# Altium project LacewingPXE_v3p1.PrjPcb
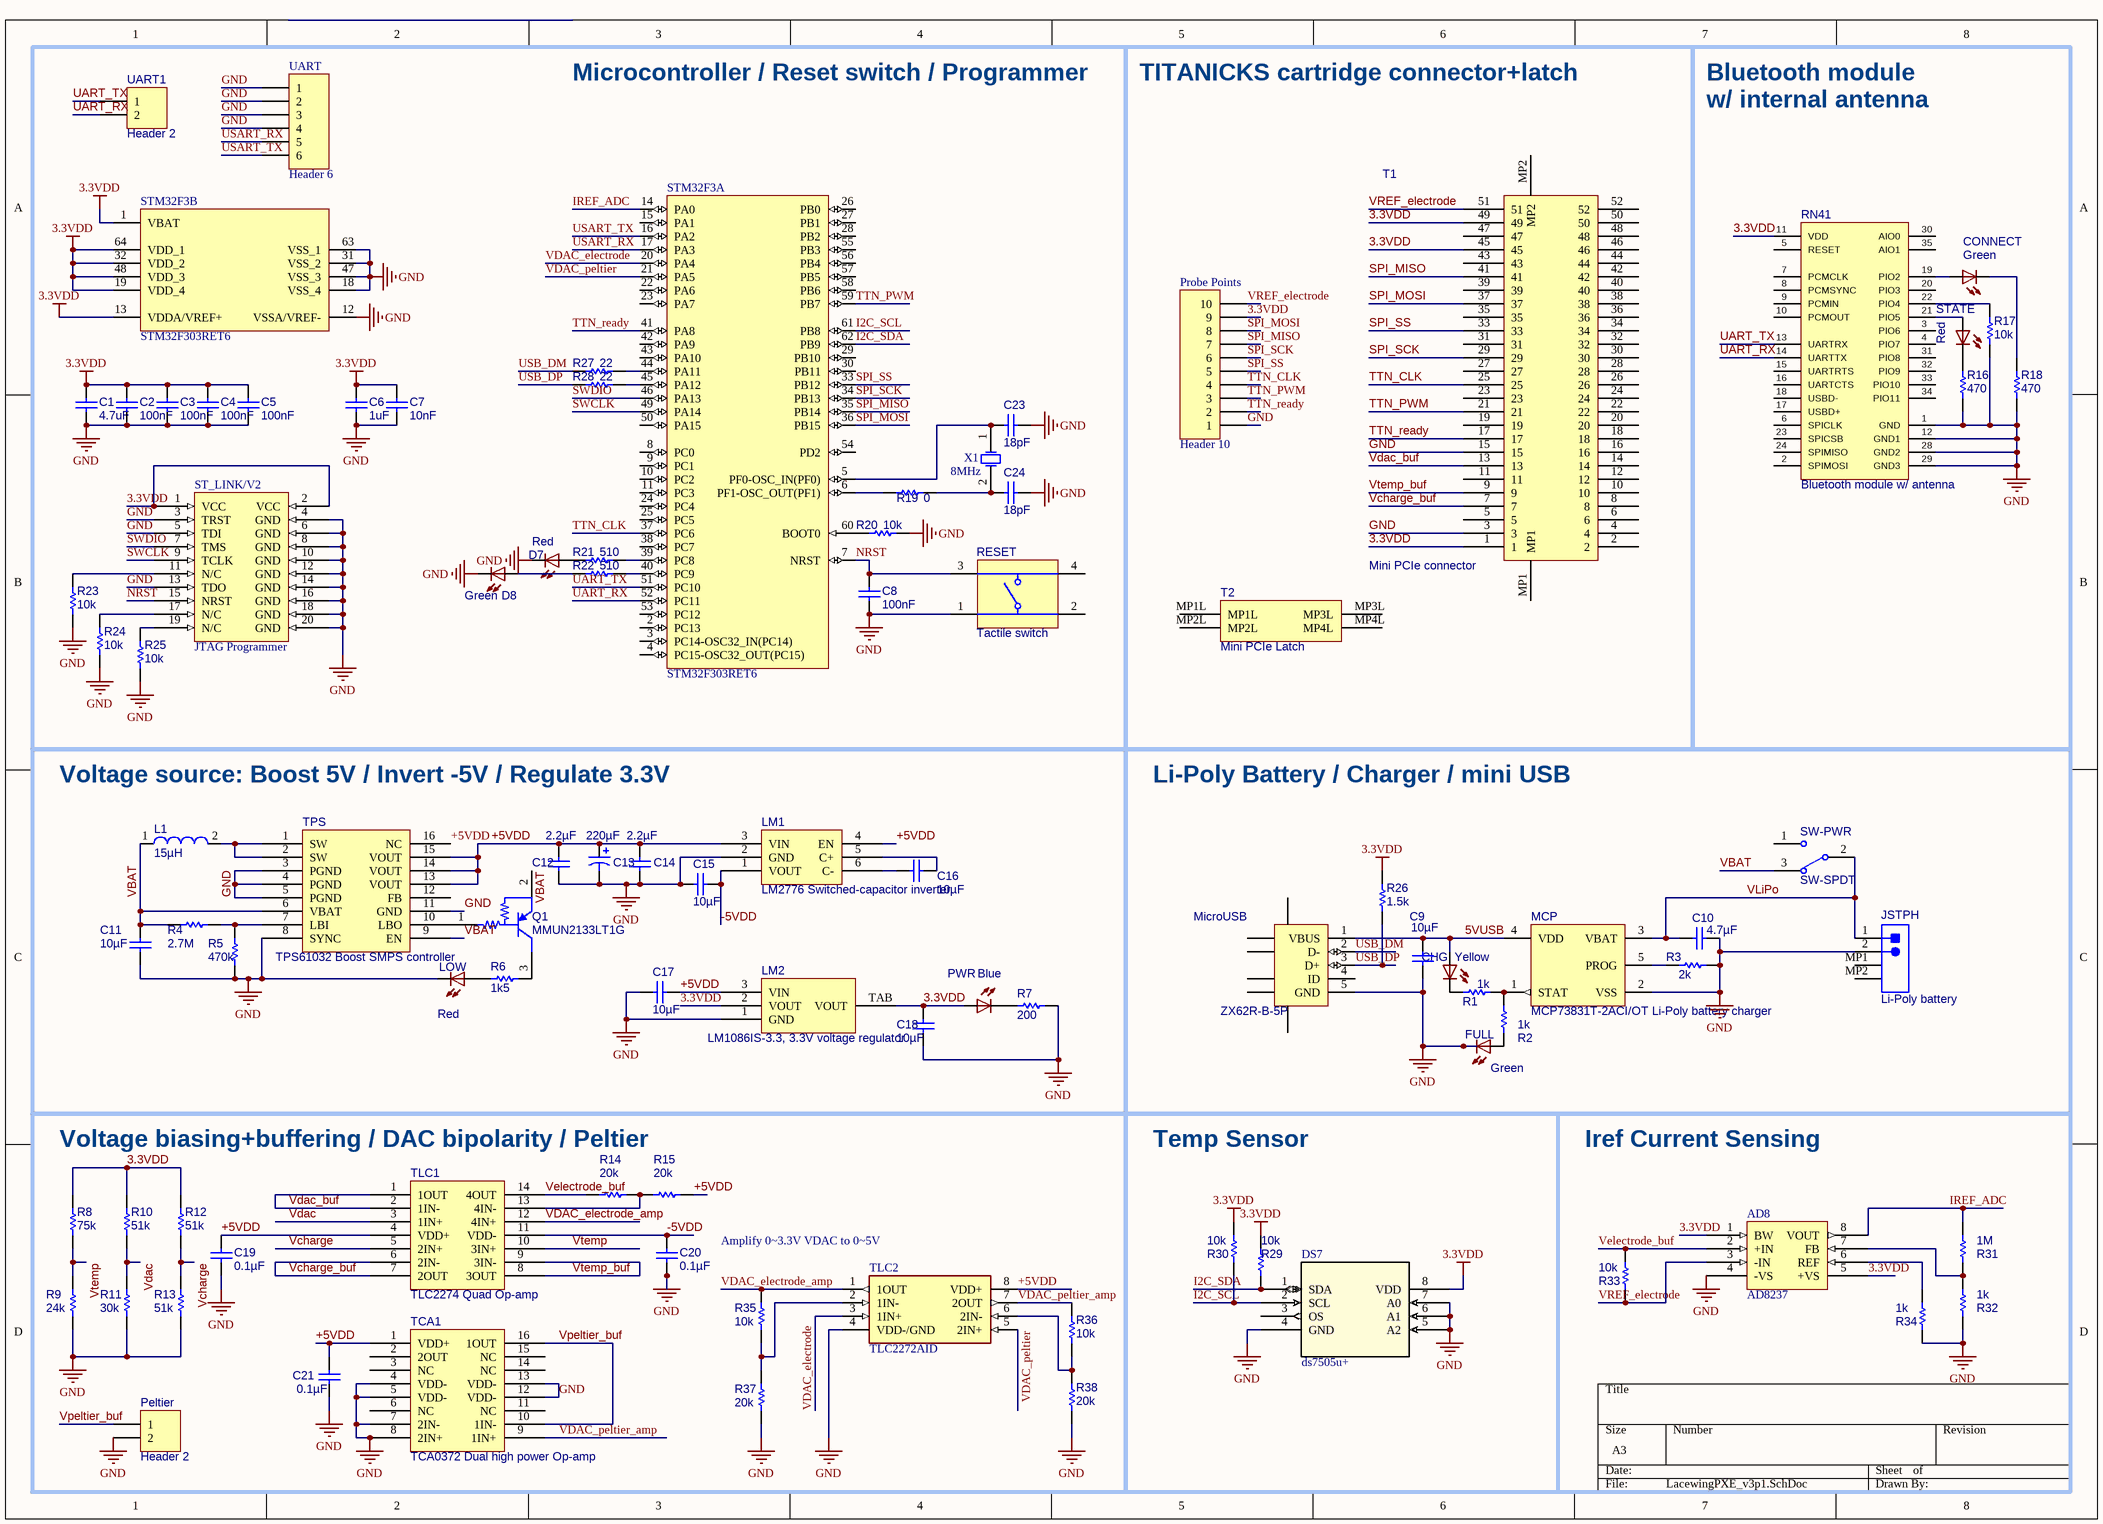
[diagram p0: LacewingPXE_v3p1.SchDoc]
1 sheet, 94 parts. Net scope: global (net labels, ports and power ports of the same name join across sheets).
Board file: LacewingPXE_v3p1.PcbDoc

## Sheet LacewingPXE_v3p1.SchDoc
size A3

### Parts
AD8  AD8237  [ADI-RM-8_N]
C1  4.7uF  [CAPC0603(1608)100_N]
C2  100nF  [CAPC0603(1608)100_N]
C3  100nF  [CAPC0603(1608)100_N]
C4  100nF  [CAPC0603(1608)100_N]
C5  100nF  [CAPC0603(1608)100_N]
C6  1uF  [CAPC0603(1608)100_N]
C7  10nF  [CAPC0603(1608)100_N]
C8  100nF  [CAPC0603(1608)100_N]
C9  10µF  [CAPC0805(2012)75_N]
C10  4.7µF  [CAPC0603(1608)100_N]
C11  10µF  [CAPC0805(2012)75_N]
C12  2.2µF  [CAPC0805(2012)75_N]
C13  220µF  [AVX-CAPC7343_V]
C14  2.2µF  [CAPC0805(2012)75_N]
C15  10µF  [CAPC0805(2012)75_N]
C16  10µF  [CAPC0805(2012)75_N]
C17  10µF  [CAPC0805(2012)75_N]
C18  10µF  [CAPC0805(2012)75_N]
C19  0.1µF  [CAPC0603(1608)100_N]
C20  0.1µF  [CAPC0603(1608)100_N]
C21  0.1µF  [CAPC0603(1608)100_N]
C23  18pF  [CAPC0603(1608)100_N]
C24  18pF  [CAPC0603(1608)100_N]
CHG  Yellow  [LED-0603]
CONNECT  Green  [LED-0603]
D7  Red  [LED-0603]
D8  Green  [LED-0603]
DS7  ds7505u+  [21-0036K]
FULL  Green  [LED-0603]
JSTPH  Li-Poly battery  [JST- S2B-PH-SM4-TB(LF)(SN)-2_V]
L1  15µH  [WE-PD 1050]
LM1  LM2776 Switched-capacitor inverter  [TI-DBV6_M]
LM2  LM1086IS-3.3, 3.3V voltage regulator  [TS3B_M]
LOW  Red  [LED-0603]
MCP  MCP73831T-2ACI/OT Li-Poly battery charger  [SOT-23-OT5_M]
MicroUSB  ZX62R-B-5P  [HIRO-ZX62R-B-5P_V]
Peltier  Header 2  [HDR1X2]
Probe_Points  Header 10  [HDR1X10]
PWR  Blue  [LED-0603]
Q1  MMUN2133LT1G  [ONSC-SOT-23-3-318-08_V]
R1  1k  [RESC0603(1608)_N]
R2  1k  [RESC0603(1608)_N]
R3  2k  [RESC0603(1608)_N]
R4  2.7M  [RESC0603(1608)_N]
R5  470k  [RESC0603(1608)_N]
R6  1k5  [RESC0603(1608)_N]
R7  200  [RESC0603(1608)_N]
R8  75k  [RESC0603(1608)_N]
R9  24k  [RESC0603(1608)_N]
R10  51k  [RESC0603(1608)_N]
R11  30k  [RESC0603(1608)_N]
R12  51k  [RESC0603(1608)_N]
R13  51k  [RESC0603(1608)_N]
R14  20k  [RESC0603(1608)_N]
R15  20k  [RESC0603(1608)_N]
R16  470  [RESC0603(1608)_N]
R17  10k  [RESC0603(1608)_N]
R18  470  [RESC0603(1608)_N]
R19  0  [RESC0603(1608)_N]
R20  10k  [RESC0603(1608)_N]
R21  510  [RESC0603(1608)_N]
R22  510  [RESC0603(1608)_N]
R23  10k  [RESC0603(1608)_N]
R24  10k  [RESC0603(1608)_N]
R25  10k  [RESC0603(1608)_N]
R26  1.5k  [RESC0603(1608)_N]
R27  22  [RESC0603(1608)_N]
R28  22  [RESC0603(1608)_N]
R29  10k  [RESC0603(1608)_N]
R30  10k  [RESC0603(1608)_N]
R31  1M  [RESC0603(1608)_N]
R32  1k  [RESC0603(1608)_N]
R33  10k  [RESC0603(1608)_N]
R34  1k  [RESC0603(1608)_N]
R35  10k  [RESC0603(1608)_N]
R36  10k  [RESC0603(1608)_N]
R37  20k  [RESC0603(1608)_N]
R38  20k  [RESC0603(1608)_N]
RESET  Tactile switch  [OMRON-B3F-1000-4_V]
RN41  Bluetooth module w/ antenna  [RN41]
ST_LINK/V2  JTAG Programmer  [JTAG2]
STATE  Red  [LED-0603]
STM32F3  STM32F303RET6  [STM-LQFP64_V]  (parts A,B of 2)
SW-PWR  SW-SPDT  [SWITCH SPDT CS12ANW03]
T1  Mini PCIe connector  [Molex Conn-67910]
T2  Mini PCIe Latch  [Molex Latch-48099]
TCA1  TCA0372 Dual high power Op-amp  [ONSC-SOIC-16-751G-03_V]
TLC1  TLC2274 Quad Op-amp  [TI-D14_M]
TLC2  TLC2272AID  [SOIC127P600X175-8N]
TPS  TPS61032 Boost SMPS controller  [PW0016A_M]
UART  Header 6  [HDR1X6]
UART1  Header 2  [HDR1X2]
X1  8MHz  [QCL]

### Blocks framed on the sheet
Microcontroller / Reset switch / Programmer: C1-C8 C23 C24 D7 D8 R19-R25 R27 R28 RESET ST_LINK/V2 STM32F3 UART UART1 X1
TITANICKS cartridge connector+latch: Probe_Points T1 T2
Voltage source: Boost 5V / Invert -5V / Regulate 3.3V: C11-C18 L1 LM1 LM2 LOW PWR Q1 R4-R7 TPS
Li-Poly Battery / Charger / mini USB: C9 C10 CHG FULL JSTPH MCP MicroUSB R1-R3 R26 SW-PWR
Voltage biasing+buffering / DAC bipolarity / Peltier: C19-C21 Peltier R8-R15 R35-R38 TCA1 TLC1 TLC2

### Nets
3.3VDD: AD8.1(BW) AD8.5(+VS) C1.1 C2.1 C3.1 C4.1 C5.1 C6.1 C7.1 C18.2 DS7.8(VDD) LM2.2(VOUT) LM2.TAB(VOUT) Probe_Points.9 PWR.A R8.1 R10.1 R12.1 R26.2 R29.2 R30.2 RN41.11(VDD) ST_LINK/V2.1(VCC) ST_LINK/V2.2(VCC) STM32F3.1(VBAT) STM32F3.13(VDDA/VREF+) STM32F3.19(VDD_4) STM32F3.32(VDD_2) STM32F3.48(VDD_3) STM32F3.64(VDD_1) T1.1 T1.45 T1.49
GND: AD8.4(-VS) C1.2 C2.2 C3.2 C4.2 C5.2 C6.2 C7.2 C8.2 C9.1 C10.1 C11.1 C12.1 C13.2 C14.1 C15.2 C17.2 C18.1 C19.1 C20.1 C21.1 C23.2 C24.2 D7.C D8.C DS7.4(GND) DS7.5(A2) DS7.6(A1) DS7.7(A0) FULL.C JSTPH.2 LM1.2(GND) LM2.1(GND) LOW.C MCP.2(VSS) MicroUSB.5(GND) Peltier.2 Probe_Points.1 R3.2 R5.2 R7.2 R9.2 R11.2 R13.2 R16.1 R17.1 R18.1 R20.2 R23.1 R24.1 R25.1 R32.1 R34.1 R37.1 R38.1 RESET.1 RN41.1(GND) RN41.12(GND1) RN41.28(GND2) RN41.29(GND3) ST_LINK/V2.3(TRST) ST_LINK/V2.4(GND) ST_LINK/V2.5(TDI) ST_LINK/V2.6(GND) ST_LINK/V2.8(GND) ST_LINK/V2.10(GND) ST_LINK/V2.12(GND) ST_LINK/V2.13(TDO) ST_LINK/V2.14(GND) ST_LINK/V2.16(GND) ST_LINK/V2.18(GND) ST_LINK/V2.20(GND) STM32F3.12(VSSA/VREF-) STM32F3.18(VSS_4) STM32F3.31(VSS_2) STM32F3.47(VSS_3) STM32F3.63(VSS_1) T1.3 T1.15 TCA1.4(VDD-) TCA1.5(VDD-) TCA1.7(2IN-) TCA1.8(2IN+) TCA1.12(VDD-) TCA1.13(VDD-) TLC2.4(VDD-/GND) TPS.3(PGND) TPS.4(PGND) TPS.5(PGND) TPS.8(SYNC) TPS.11(GND) UART.1 UART.2 UART.3 UART.4
5VUSB: C9.2 CHG.A MCP.4(VDD) MicroUSB.1(VBUS)
+5VDD: C12.2 C13.1 C14.2 C17.1 C19.2 C21.2 LM1.3(VIN) LM1.4(EN) LM2.3(VIN) R15.2 TCA1.1(VDD+) TLC1.4(VDD+) TLC2.8(VDD+) TPS.13(VOUT) TPS.14(VOUT) TPS.15(VOUT) TPS.16(NC)
-5VDD: C15.1 C20.2 LM1.1(VOUT) TLC1.11(VDD-)
I2C_SCL: DS7.2(SCL) R30.1 STM32F3.61(PB8)
I2C_SDA: DS7.1(SDA) R29.1 STM32F3.62(PB9)
IREF_ADC: AD8.8(VOUT) R31.2 STM32F3.14(PA0)
NRST: C8.1 RESET.3 ST_LINK/V2.15(NRST) STM32F3.7(NRST)
SPI_MISO: Probe_Points.7 STM32F3.35(PB14) T1.41
SPI_MOSI: Probe_Points.8 STM32F3.36(PB15) T1.37
SPI_SCK: Probe_Points.6 STM32F3.34(PB13) T1.29
SPI_SS: Probe_Points.5 STM32F3.33(PB12) T1.33
SWCLK: ST_LINK/V2.9(TCLK) STM32F3.49(PA14)
SWDIO: ST_LINK/V2.7(TMS) STM32F3.46(PA13)
TTN_CLK: Probe_Points.4 STM32F3.37(PC6) T1.25
TTN_PWM: Probe_Points.3 STM32F3.59(PB7) T1.21
TTN_ready: Probe_Points.2 STM32F3.41(PA8) T1.17
UART_RX: RN41.14(UARTTX) STM32F3.52(PC11) UART1.2
UART_TX: RN41.13(UARTRX) STM32F3.51(PC10) UART1.1
USART_RX: STM32F3.17(PA3) UART.5
USART_TX: STM32F3.16(PA2) UART.6
USB_DM: MicroUSB.2(D-) R27.1
USB_DP: MicroUSB.3(D+) R26.1 R28.1
VBAT: C11.2 L1.1 Q1.2(E) R4.2 SW-PWR.3 TPS.6(VBAT) TPS.9(EN)
Vcharge: R12.2 R13.1 TLC1.5(2IN+)
Vcharge_buf: T1.7 TLC1.6(2IN-) TLC1.7(2OUT)
Vdac: R10.2 R11.1 TLC1.3(1IN+)
Vdac_buf: T1.13 TLC1.1(1OUT) TLC1.2(1IN-)
VDAC_electrode: STM32F3.20(PA4) TLC2.3(1IN+)
VDAC_electrode_amp: R35.2 TLC1.12(4IN+) TLC2.1(1OUT)
VDAC_peltier: STM32F3.21(PA5) TLC2.5(2IN+)
VDAC_peltier_amp: R36.2 TCA1.9(1IN+) TLC2.7(2OUT)
Velectrode_buf: AD8.2(+IN) R14.1 R33.2 TLC1.14(4OUT)
VLiPo: C10.2 JSTPH.1 MCP.3(VBAT) SW-PWR.2
Vpeltier_buf: Peltier.1 TCA1.10(1IN-) TCA1.16(1OUT)
VREF_electrode: AD8.3(-IN) Probe_Points.10 R33.1 T1.51
Vtemp: R8.2 R9.1 TLC1.10(3IN+)
Vtemp_buf: T1.9 TLC1.8(3OUT) TLC1.9(3IN-)
NetAD8_6: AD8.6(REF) R34.2
NetAD8_7: AD8.7(FB) R31.1 R32.2
NetC16_1: C16.1 LM1.5(C+)
NetC16_2: C16.2 LM1.6(C-)
NetC23_1: C23.1 STM32F3.5(PF0-OSC_IN(PF0)) X1.1(OSC1)
NetC24_1: C24.1 R19.1 X1.2(OSC2)
NetCHG_C: CHG.C R1.1
NetCONNECT_A: CONNECT.A RN41.19(PIO2)
NetCONNECT_C: CONNECT.C R18.2
NetD7_A: D7.A R21.1
NetD8_A: D8.A R22.1
NetFULL_A: FULL.A R2.1
NetL1_2: L1.2 TPS.1(SW) TPS.2(SW)
NetLOW_A: LOW.A R6.1
NetMCP_1: MCP.1(STAT) R1.2 R2.2
NetMCP_5: MCP.5(PROG) R3.1
NetPWR_C: PWR.C R7.1
NetQ1_1: Q1.1(B) TPS.10(LBO)
NetQ1_3: Q1.3(C) R6.2
NetR4_1: R4.1 R5.1 TPS.7(LBI)
NetR14_2: R14.2 R15.1 TLC1.13(4IN-)
NetR16_2: R16.2 STATE.C
NetR17_2: R17.2 RN41.22(PIO4)
NetR19_2: R19.2 STM32F3.6(PF1-OSC_OUT(PF1))
NetR20_1: R20.1 STM32F3.60(BOOT0)
NetR21_2: R21.2 STM32F3.39(PC8)
NetR22_2: R22.2 STM32F3.40(PC9)
NetR23_2: R23.2 ST_LINK/V2.11(N/C)
NetR24_2: R24.2 ST_LINK/V2.17(N/C)
NetR25_2: R25.2 ST_LINK/V2.19(N/C)
NetR27_2: R27.2 STM32F3.44(PA11)
NetR28_2: R28.2 STM32F3.45(PA12)
NetR35_1: R35.1 R37.2 TLC2.2(1IN-)
NetR36_1: R36.1 R38.2 TLC2.6(2IN-)
NetRN41_21: RN41.21(PIO5) STATE.A

Not connected (* = marked no-connect by the designer): DS7 3(OS); JSTPH MP1 MP2; MicroUSB 4(ID) 6(SHLD) 7(SHLD) 8(SHLD) 9(SHLD) 10(SHLD) 11(SHLD); RESET 2 4; RN41 2(SPIMOSI) 3(PIO6) 4(PIO7) 5(RESET) 6(SPICLK) 7(PCMCLK) 8(PCMSYNC) 9(PCMIN) 10(PCMOUT) 15(UARTRTS) 16(UARTCTS) 17(USBD+) 18(USBD-) 20(PIO3) 23(SPICSB) 24(SPIMISO) 30(AIO0) 31(PIO8) 32(PIO9) 33(PIO10) 34(PIO11) 35(AIO1); STM32F3 2(PC13) 3(PC14-OSC32_IN(PC14)) 4(PC15-OSC32_OUT(PC15)) 8(PC0) 9(PC1) 10(PC2) 11(PC3) 15(PA1) 22(PA6) 23(PA7) 24(PC4) 25(PC5) 26(PB0) 27(PB1) 28(PB2) 29(PB10) 30(PB11) 38(PC7) 42(PA9) 43(PA10) 50(PA15) 53(PC12) 54(PD2) 55(PB3) 56(PB4) 57(PB5) 58(PB6); SW-PWR 1; T1 2 4 5 6 8 10 11 12 14 16 18 19 20 22 23 24 26 27 28 30 31 32 34 35 36 38 39 40 42 43 44 46 47 48 50 52 MP1 MP2; T2 MP1L MP2L MP3L MP4L; TCA1 2(2OUT) 3(NC) 6(NC) 11(NC) 14(NC) 15(NC); TPS 12(FB)

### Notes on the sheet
- Bluetooth module
- w/ internal antenna
- Temp Sensor
- Iref Current Sensing
- Amplify 0~3.3V VDAC to 0~5V

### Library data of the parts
C1-C8 C23 C24 = CMP-1035-00032-1: Ceramic CAP0603 (1608 Metric) Thickness 1mm SMD; Case-EIA: 0603
C9 C11 C12 C14-C18 = CMP-1036-00002-1: Ceramic CAP0805 (2012 Metric) Thickness 0.75mm SMD; Case-EIA: 0805; Rated Voltage: 10 V
C10 = CMP-1035-00032-1: Ceramic CAP0603 (1608 Metric) Thickness 1mm SMD; Case-EIA: 0603; Rated Voltage: 10 V
C13 = CMP-0279-00002-1: Capacitor, Tantalum, 220uF 10% 10V MCCT-D (7343-31); PartNumber: TAJD227K010R; Manufacturer: AVX; Polarity: Polarized
C19-C21 = CAP: Ceramic CAP0603 (1608 Metric) Thickness 1mm SMD; Case-EIA: 0603
CHG CONNECT FULL LOW STATE = LED0603: LED SMD 0603
D7 D8 PWR = LED0603: LED SMD 0603; RS Order: 654-5666
DS7 = ds7505u+: No Description Available; Vendor: Maxim Integrated Products; Built_By: EMA_UL_Team; Type: DEV
JSTPH = CN-1P-2M-R2: JST PH 2-pin 2-holder SMD
L1 = CMP-1396-00032-1: SMD-Shielded Power Inductor WE-PD 7447714150, L=15 µH
LM1 = LM2776
LM2 = LM1086IS-3.3
MCP = CMP-0133-00143-1: Miniature Single-Cell, Fully Integrated Li-Ion, Li-Polymer Charge Management Controller, 4.2V, 5-Pin SOT-23, Industrial Temperature, Tape and Reel
MicroUSB = CMP-0031-00001-1: Connector; USBMicro-B,Reverse type, SMT; 5 Position; Right Angle
Peltier UART1 = Header 2: Header, 2-Pin
Probe_Points = Header 10: Header, 10-Pin
Q1 = CMP-0630-00284-1: Digital Transistor (BRT), R1=4.7 kOhm, R2=47 kOhm, PNP Transistor, 3-Pin SOT-23, Pb-Free, Tape and Reel
R1-R38 = CMP-1012-00514-1: RES0603 (1608 Metric)  SMD; Case-EIA: 0603
RESET = SW-SPST-4_A: ORMON B3F-10XX
RN41 = BLUETOOTH-RN41: Bluetooth SMD module
ST_LINK/V2 = JTAG
STM32F3 = STM32F303RBT6_1: ARM Cortex-M4 32-bit MCU, 128 KB Flash, 32 KB Internal RAM, 52 I/Os, 64-pin LQFP, -40 to 85 degC, Tray; D/A Converter: 2x12-bit (2 Channel); FLASH Size (Prog) (kB): 128; I/Os (High Current): 52; Internal RAM Size (kB): 32; Operating Frequency(F) (Processor speed) (MHz): 72; Supply Voltage(Vcc) min (V): 2
SW-PWR = SW-SPDT: Switch SPDT CS12ANW03
TCA1 = TCA0372
TLC1 = TLC2274
TLC2 = TLC2272AID: Integrated Circuit; Manufacturer_Name: Texas Instruments
TPS = TPS61032
UART = Header 6: Header, 6-Pin
X1 = XTAL: Crystal Oscillator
